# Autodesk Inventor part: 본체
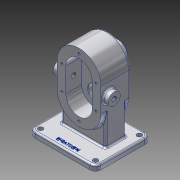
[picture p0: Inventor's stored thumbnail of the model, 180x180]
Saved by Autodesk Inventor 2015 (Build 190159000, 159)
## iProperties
Created: 2020-09
Part Number: 본체
Material: 알루미늄 6061
Document SubType Name: Modeling
Designer: LINEART-A501
Density: 2.7 g/cm^3
Appearance: 알루미늄 - 평지
Mass: 1440.46 g
Surface Area: 785.636 cm^2
Volume: 533.505 cm^3
Author: LINEART-A501
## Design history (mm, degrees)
sketch "스케치1"
  geometry: L1 (40, 62)-(-40, 62); L2 (-40, 62)-(-40, -62); L3 (-40, -62)-(40, -62); L4 (40, -62)-(40, 62); L5 (40, 62)-(-40, -62); L6 (-40, 62)-(40, -62); 1 further point
  constraints: 12 end point, 2 midpoint, 2 parallel, 1 horizontal, 1 perpendicular
  dimensions: "d0" = 80 distance of L3.end L2.end; "d1" = 124 distance of L2.end L1.end
extrude "돌출1" new body sketch "스케치1" distance "d2" = 53; taper "d3" = 0 deg
fillet "모깎기1" dims "d4" = 40
sketch "스케치2"
  geometry: L1 (0, 22)-(0, -22); L2 (-24, 22)-(-24, -22); L3 (24, -22)-(24, 22); L4 (0, 22)-(44, 22); A1 r 40 centre (0, 22) between (40, 22) and (-40, 22) reference; A2 r 24 centre (0, 22) between (24, 22) and (-24, 22); A3 r 24 centre (0, -22) between (-24, -22) and (24, -22); 2 further points
  constraints: 10 end point, 4 point on circle, 4 tangent, 2 centre point, 1 horizontal, 1 midpoint, 1 parallel, 1 perpendicular, 1 vertical
  dimensions: "d5" = 44 distance of L1.start L1.end; "d6" = 90 deg angle of L1 L4 (derived); "d7" = 48 diameter of A3
extrude "돌출2" cut sketch "스케치2" distance "d8" = 29; taper "d9" = 0 deg
sketch "스케치3"
  geometry: A1 r 24 centre (0, 22) between (24, 22) and (-24, 22) reference; A2 r 24 centre (0, -22) between (-24, -22) and (24, -22) reference; 3 further points
  constraints: 2 coincident
hole "구멍1" sketch "스케치3" at (0, 22), (0, -22) diameter "d10" = 25; stored, may be unused: countersink angle "d14" = 90 deg, drill point angle "d16" = 0 deg; dims "d11" = 6, "d12" = 4, "d13" = 2, "d15" = 15
chamfer "모따기1" distance "d17" = 1; stored, may be unused: second distance "d18" = 2, angle "d19" = 45 deg
sketch "스케치4"
  geometry: C1 r 12.5 at (0, 22) reference; C2 r 19 at (0, 22); 1 further point
  constraints: 1 centre point, 1 coincident
  dimensions: "d20" = 38 diameter of C2
extrude "돌출3" join sketch "스케치4" distance "d21" = 17; taper "d22" = 0 deg
sketch "스케치5"
  geometry: L1 (3, -17)-(41, -17) reference; L2 (22, -17)-(36, -17); L3 (22, -17)-(36, -17); L4 (36, -17)-(36, -10.2); L5 (35.5, -9.7)-(30.5, -9.7); L6 (62, 0)-(22, 0) reference; L7 (30.5, -9.7)-(30.5, 9); L8 (34.5, 9)-(9.5, 9) reference; L9 (30.5, 9)-(22, 9); L10 (30.5, 9)-(39, 9); L11 (22, 9)-(22, -17); L12 (22, -17)-(36, -17); A1 r 0.5 centre (35.5, -10.2) between (36, -10.2) and (35.5, -9.7); 2 further points
  constraints: 18 end point, 4 collinear, 3 perpendicular, 3 point on line, 2 horizontal, 2 point on circle, 2 tangent, 1 centre point, 1 midpoint, 1 parallel
  dimensions: "d38" = 14 distance of L2.start L2.end; "d39" = 0 distance between parallel lines of L2 L3 (derived); "d40" = 7.3 distance of L2.end point (36, -9.7); "d41" = 90 deg angle of L4 L2 (derived); "d42" = 5.5 distance of point (36, -9.7) L5.end; "d43" = 90 deg angle of L5 L4 (derived); "d44" = 8.5 distance of L7.end L9.end; "d45" = 180 deg angle of L9 L10 (derived); "d47" = 0.5 radius of A1
revolve "회전1" sketch "스케치5" stored, may be unused: angle "d46" = 90 deg
chamfer "모따기3" distance "d48" = 0.7; stored, may be unused: second distance "d49" = 2, angle "d50" = 30 deg
sketch "스케치6"
  geometry: C1 r 8.5 at (0, 22) reference; C2 r 13.5 at (0, -22) reference; 3 further points
  constraints: 2 vertical alignment
  dimensions: "d51" = 31 distance of C1.centre point (0, 53); "d59" = 31 distance of point (0, -53) C2.centre
hole "구멍3" sketch "스케치6" at (0, 53), (0, -53) diameter "d52" = 4.134; stored, may be unused: countersink angle "d56" = 90 deg, drill point angle "d58" = 118 deg; dims "d53" = 10, "d54" = 4, "d55" = 2, "d57" = 12
sketch "스케치7"
  geometry: C1 r 8.5 at (0, 22) reference; 3 further points
  constraints: 2 horizontal alignment
  dimensions: "d60" = 31 distance of point (-31, 22) C1.centre; "d71" = 31 distance of point (31, 22) C1.centre
hole "구멍4" sketch "스케치7" at (-31, 22), (31, 22) diameter "d61" = 4.134; stored, may be unused: countersink angle "d65" = 90 deg, drill point angle "d67" = 118 deg; dims "d62" = 10, "d63" = 4, "d64" = 2, "d66" = 12
sketch "스케치8"
  geometry: L1 (0, 0)-(0, 44) reference; L2 (-53, 0)-(-53, 44) reference; C1 r 11 at (-39, 22); 2 further points
  constraints: 1 centre point, 1 horizontal alignment, 1 midpoint
  dimensions: "d72" = 22 diameter of C1; "d73" = 14 distance from line of C1.centre L2
extrude "돌출4" join sketch "스케치8" distance "d74" = 10; taper "d75" = 0 deg
hole "구멍5" diameter "d78" = 8.376; stored, may be unused: countersink angle "d82" = 90 deg, drill point angle "d84" = 0 deg; dims "d76" = 10, "d77" = 10, "d79" = 20, "d80" = 4, "d81" = 2, "d83" = 27.3
fillet "모깎기3" dims "d85" = 3
node "작업 평면1"
sketch "스케치9"
  geometry: L1 (0, 0)-(0, 33); L2 (0, 0)-(33, 0); L3 (60, 83)-(-60, 83); L4 (-60, 83)-(-60, -17); L5 (-60, -17)-(60, -17); L6 (60, -17)-(60, 83); L7 (60, 83)-(-60, -17); L8 (-60, 83)-(60, -17)
  constraints: 16 end point, 2 horizontal, 2 midpoint, 2 parallel, 2 perpendicular, 1 vertical
  dimensions: "d87" = 33 distance of L1.start L1.end; "d88" = 90 deg angle of L2 L1 (derived); "d89" = 120 distance of L5.end L4.end; "d90" = 100 distance of L4.end L3.end
extrude "돌출5" join sketch "스케치9" distance "d91" = 10; taper "d92" = 0 deg
fillet "모깎기4" dims "d93" = 10
sketch "스케치10"
  geometry: A1 r 10 centre (-50, -73) between (-60, -73) and (-50, -83) reference; 2 further points
  constraints: 1 coincident
hole "구멍6" sketch "스케치10" at (-50, -73) diameter "d94" = 9; stored, may be unused: countersink angle "d98" = 90 deg, drill point angle "d100" = 0 deg; dims "d95" = 20, "d96" = 4, "d97" = 2, "d99" = 27.3
fillet "모깎기5" dims "d107" = 3
sketch "스케치11"
  geometry: L1 (-60, 7)-(-60, -73) reference; L2 (-50, -83)-(50, -83) reference; 2 further points
  constraints: 1 other
  dimensions: "d108" = 60 distance from line of point (0, -73) L1; "d109" = 10 distance from line of L2 point (0, -73)
feature "엠보싱1" sketch "스케치11" dims "d0" = 80, "d1" = 124, "d5" = 44, "d6" = 90 deg (derived), "d7" = 48, "d110" = 0.5, "d111" = 0
sketch "스케치12"
  geometry: L1 (-90, -17)-(-90, 8); L2 (-90, -7)-(-90, 73) reference; L3 (-90, 8)-(-60, 8); L4 (-90, 8)-(-60, 8); L5 (-60, 8)-(-60, 45); L6 (-60, 45)-(-90, 45); L7 (-90, 45)-(-90, 8); 1 further point
  constraints: 12 end point, 2 horizontal, 2 perpendicular, 1 collinear, 1 point on line
  dimensions: "d112" = 25 distance of L1.start L1.end; "d113" = 30 distance of L1.end L3.end; "d114" = 0 distance between parallel lines of L3 L4 (derived); "d115" = 37 distance of L3.end L5.end; "d116" = 90 deg angle of L5 L3 (derived); "d117" = 30 distance of L5.end L6.end; "d118" = 90 deg angle of L6 L5 (derived)
extrude "돌출6" join sketch "스케치12" stored distance "d119" = 80; taper "d120" = 0 deg
sketch "스케치13"
  geometry: L1 (0, 20)-(0, 58); L2 (0, 20)-(27.51, 20); L3 (80, 20)-(80, 58); L4 (80, 20)-(52.49, 20); L5 (52.49, 20)-(80, 20) reference; A1 r 40 centre (40, 58) between (0, 58) and (80, 58) reference; A2 r 40 centre (40, 58) between (0, 58) and (27.51, 20); A3 r 40 centre (40, 58) between (52.49, 20) and (80, 58); 1 further point
  constraints: 8 end point, 6 point on circle, 3 tangent, 2 centre point, 2 concentric, 2 vertical, 1 collinear, 1 perpendicular
extrude "돌출7" join sketch "스케치13" distance "d121" = 37; taper "d122" = 0 deg
fillet "모깎기6" dims "d123" = 3
fillet "모깎기7" dims "d124" = 3
node "솔리드1"
pattern_linear "직사각형 패턴1" dims "d70" = 44
mirror "대칭1"
pattern_linear "직사각형 패턴2" dims "d103" = 100
